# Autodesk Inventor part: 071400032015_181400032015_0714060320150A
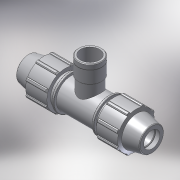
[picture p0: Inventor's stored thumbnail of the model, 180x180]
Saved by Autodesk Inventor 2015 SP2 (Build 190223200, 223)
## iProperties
Created: 2017-02
Part Number: 071400032015_181400032015_0714060320150A
Material: PVC-Piping
Description: PLASSON TEE WITH THREADED FEMALE OFFTAKE 32-1.1/2"-32
Document SubType Name: Modeling
Designer: KIM
Mass: 92.6774 g
Surface Area: 199.44 cm^2
Volume: 66.1981 cm^3
Density: 1.4 g/cm^3
Appearance: Smooth - White
Author: KIM
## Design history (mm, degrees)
derived "07140.ipt"
feature "Solid1::07140.ipt"
feature "Solid2::07140.ipt"
tag "TaggingFeature1"
body "Solid1"
other parameters: "d2" = 32, "d4" = 7.58333, "d5" = 21.84, "d7" = 64, "d11" = 3.03333, "d13" = 120 deg, "d14" = 48, "d15" = 12 deg, "d16" = 55.68, "d18" = 1.6, "d19" = 35 deg, "d20" = 17.5 deg, "d21" = 59.52, "d23" = 0, "d25" = 360 deg, "d27" = 1.28, "d33" = 0.64, "d42" = 32.76, "d43" = 1.92, "d46" = 0.96, "d68" = 5.46, "d72" = 71, "d76" = 44.845, "d80" = 1.34535, "d91" = 48, "d93" = 67, "d95" = 28.8, "d112" = 25, "d115" = 56.05625, "d116" = 135 deg, "d117" = 51.57175, "d118" = 182, "d119" = 28.8, "d121" = 0, "d122" = 28.8, "d124" = 0, "d128" = 0, "d129" = 3.2, "d130" = 7.5, "d131" = 0.3, "d132" = 0.3, "d133" = 56.05625, "d_" = 32, "E_" = 64, "A_" = 71, "l_" = 67, "l_2" = 25, "Rp_" = 44.845, "H_" = 182
